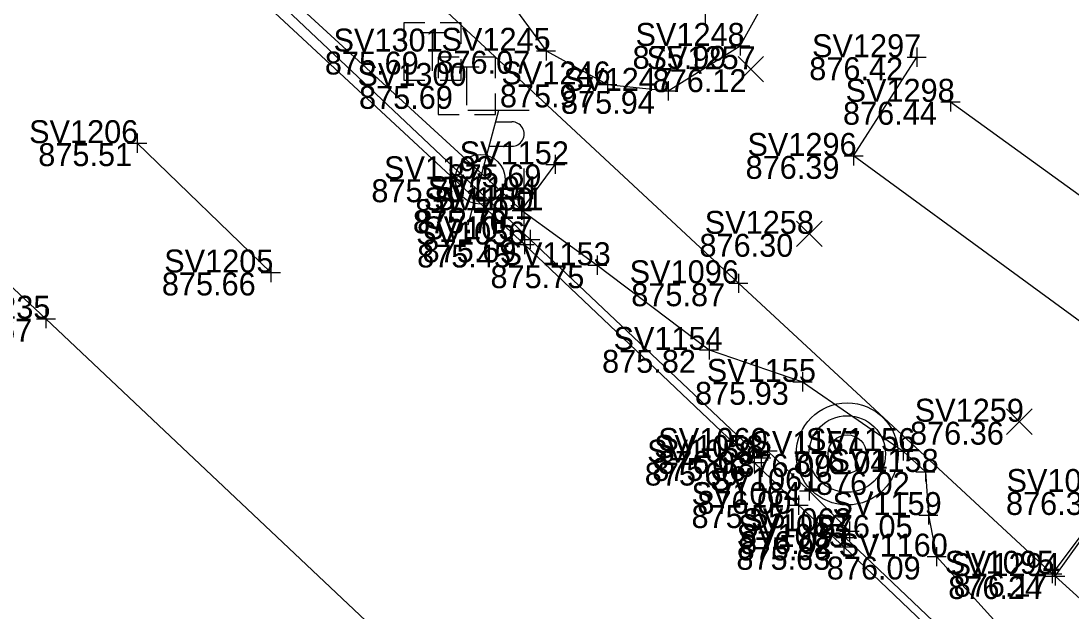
# Model space of a CAD drawing. Extents: x 1480001 to 1480402, y 379235 to 379603.
# Drawn here: x 1480223.3 to 1480278.2, y 379360.8 to 379391.7 of the extents above; entities that cross this region are included whole.
import ezdxf

# ---------------------------------------------------------------- set-up
doc = ezdxf.new("R2010")
doc.units = 0
for name, color, linetype in [('BD_X_Building', 7, 'Continuous'), ('DR_X_Cells', 7, 'Continuous'), ('GK_Drainage_Nodes', 7, 'Continuous'), ('PM_P_CL_Double_Solid', 7, 'Continuous'), ('PM_X_Lane_Line', 7, 'Continuous'), ('PV_X_Curb', 7, 'Continuous'), ('PV_X_Walk', 7, 'Continuous'), ('RD_X_Cells', 7, 'Continuous'), ('SN_X_Public', 7, 'Continuous'), ('SV_X_Random_Point', 7, 'Continuous'), ('SV_X_Shot_Marker', 7, 'Continuous'), ('SV_X_Text_Elevation', 7, 'Continuous'), ('SV_X_Text_Name', 7, 'Continuous'), ('UT_X_Misc_Cells', 7, 'Continuous'), ('UT_X_Telecom_Cells', 7, 'Continuous'), ('UT_X_Water', 7, 'Continuous'), ('VG_X_Flower_Bed', 7, 'Continuous')]:
    doc.layers.add(name, color=color, linetype=linetype)

msp = doc.modelspace()

# ---------------------------------------------------------------- linework, layer by layer
at = {"layer": 'BD_X_Building'}
msp.add_line((1480271.911, 379387.504), (1480306.519, 379362.484), dxfattribs=at)
at = {"layer": 'DR_X_Cells'}
for radius in [2.667, 2, 1]:
    msp.add_circle((1480266.509, 379369.096), radius, dxfattribs=at)
at = {"layer": 'GK_Drainage_Nodes'}
for p, q in [((1480266.509, 379371.096), (1480266.509, 379371.096)), ((1480266.509, 379369.096), (1480266.509, 379369.096)), ((1480266.509, 379369.096), (1480266.509, 379369.096)), ((1480266.509, 379369.096), (1480266.509, 379369.096)), ((1480266.509, 379367.096), (1480266.509, 379367.096))]:
    msp.add_line(p, q, dxfattribs=at)
msp.add_circle((1480266.509, 379369.096), 2, dxfattribs=at)
at = {"layer": 'PM_P_CL_Double_Solid'}
msp.add_lwpolyline([(1480349.171, 379259.048), (1480326.954, 379280.06), (1480305.568, 379299.916), (1480284.393, 379319.578), (1480263.301, 379339.268), (1480242.575, 379359.213), (1480224.612, 379376.165), (1480208.191, 379391.527)], dxfattribs=at)
at = {"layer": 'PM_X_Lane_Line'}
msp.add_line((1480236.368, 379378.582), (1480229.378, 379385.342), dxfattribs=at)
at = {"layer": 'PV_X_Curb'}
for points in [[(1480221.908, 379406.565), (1480233.156, 379396.15), (1480249.934, 379380.311), (1480262.014, 379368.886), (1480262.346, 379369.254), (1480264.513, 379367.165), (1480266.627, 379365.06), (1480266.41, 379364.736), (1480284.493, 379347.537), (1480298.919, 379333.838), (1480300.736, 379332.585), (1480315.855, 379318.308), (1480323.784, 379310.749), (1480324.548, 379310.084), (1480343.241, 379292.305), (1480360.288, 379276.242)], [(1480221.495, 379406.235), (1480232.955, 379395.538), (1480249.633, 379380.044), (1480261.648, 379368.645), (1480263.97, 379366.423), (1480266.337, 379364.241), (1480284.168, 379347.237), (1480298.679, 379333.414), (1480300.396, 379332.229), (1480315.326, 379318.045), (1480323.87, 379309.98), (1480343.087, 379291.663), (1480360.248, 379275.585)]]:
    msp.add_lwpolyline(points, dxfattribs=at)
at = {"layer": 'PV_X_Walk'}
for points in [[(1480355.123, 379297.828), (1480351.285, 379293.6), (1480334.098, 379309.328), (1480328.212, 379315.428), (1480328.737, 379316.329), (1480319.905, 379324.485), (1480307.606, 379335.13), (1480302.895, 379338.359), (1480281.823, 379358.406), (1480285.611, 379363.387), (1480280.441, 379367.109), (1480277.224, 379362.834), (1480260.819, 379378.019), (1480244.572, 379393.153), (1480235.613, 379401.335), (1480215.341, 379421.047)], [(1480304.825, 379363.469), (1480301.807, 379359.476), (1480289.404, 379368.611), (1480281.88, 379358.636), (1480277.384, 379362.714), (1480284.099, 379372.064), (1480266.845, 379384.676), (1480270.146, 379389.834)]]:
    msp.add_lwpolyline(points, dxfattribs=at)
at = {"layer": 'RD_X_Cells'}
msp.add_line((1480259.085, 379392.125), (1480259.085, 379391.593), dxfattribs=at)
at = {"layer": 'SN_X_Public'}
for p, q in [((1480249.601, 379384.014), (1480249.601, 379380.814)), ((1480249.601, 379382.414), (1480248.001, 379382.414))]:
    msp.add_line(p, q, dxfattribs=at)
at = {"layer": 'SV_X_Random_Point'}
for p, q in [((1480260.805, 379388.541), (1480262.139, 379389.876)), ((1480260.805, 379389.876), (1480262.139, 379388.541)), ((1480263.861, 379379.936), (1480265.195, 379381.271)), ((1480263.861, 379381.271), (1480265.195, 379379.936)), ((1480274.842, 379370.114), (1480276.176, 379371.449)), ((1480274.842, 379371.449), (1480276.176, 379370.114))]:
    msp.add_line(p, q, dxfattribs=at)
at = {"layer": 'SV_X_Shot_Marker'}
for p, q in [((1480250.763, 379390.67), (1480250.763, 379389.67)), ((1480260.916, 379390.926), (1480260.916, 379389.926)), ((1480250.263, 379390.17), (1480251.263, 379390.17)), ((1480250.763, 379390.17), (1480250.763, 379390.17)), ((1480260.416, 379390.426), (1480261.416, 379390.426)), ((1480260.916, 379390.426), (1480260.916, 379390.426)), ((1480270.146, 379390.334), (1480270.146, 379389.334)), ((1480269.646, 379389.834), (1480270.646, 379389.834)), ((1480270.146, 379389.834), (1480270.146, 379389.834)), ((1480253.969, 379388.913), (1480253.969, 379387.913)), ((1480253.469, 379388.413), (1480254.469, 379388.413)), ((1480253.969, 379388.413), (1480253.969, 379388.413)), ((1480257.154, 379388.576), (1480257.154, 379387.576)), ((1480256.654, 379388.076), (1480257.654, 379388.076)), ((1480257.154, 379388.076), (1480257.154, 379388.076)), ((1480271.911, 379388.004), (1480271.911, 379387.004)), ((1480271.411, 379387.504), (1480272.411, 379387.504)), ((1480271.911, 379387.504), (1480271.911, 379387.504)), ((1480229.378, 379385.842), (1480229.378, 379384.842)), ((1480228.878, 379385.342), (1480229.878, 379385.342)), ((1480229.378, 379385.342), (1480229.378, 379385.342)), ((1480266.845, 379385.176), (1480266.845, 379384.176)), ((1480251.242, 379384.735), (1480251.242, 379383.735)), ((1480266.345, 379384.676), (1480267.345, 379384.676)), ((1480266.845, 379384.676), (1480266.845, 379384.676)), ((1480250.742, 379384.235), (1480251.742, 379384.235)), ((1480251.242, 379384.235), (1480251.242, 379384.235)), ((1480249.485, 379382.337), (1480249.485, 379381.337)), ((1480249.493, 379382.328), (1480249.493, 379381.328)), ((1480248.985, 379381.837), (1480249.985, 379381.837)), ((1480248.993, 379381.828), (1480249.993, 379381.828)), ((1480249.485, 379381.837), (1480249.485, 379381.837)), ((1480249.493, 379381.828), (1480249.493, 379381.828)), ((1480249.934, 379380.811), (1480249.934, 379379.811)), ((1480249.133, 379380.044), (1480250.133, 379380.044)), ((1480249.434, 379380.311), (1480250.434, 379380.311)), ((1480249.633, 379380.544), (1480249.633, 379379.544)), ((1480249.633, 379380.044), (1480249.633, 379380.044)), ((1480249.934, 379380.311), (1480249.934, 379380.311)), ((1480253.44, 379379.463), (1480253.44, 379378.463)), ((1480236.368, 379379.082), (1480236.368, 379378.082)), ((1480252.94, 379378.963), (1480253.94, 379378.963)), ((1480253.44, 379378.963), (1480253.44, 379378.963)), ((1480235.868, 379378.582), (1480236.868, 379378.582)), ((1480236.368, 379378.582), (1480236.368, 379378.582)), ((1480260.819, 379378.519), (1480260.819, 379377.519)), ((1480260.319, 379378.019), (1480261.319, 379378.019)), ((1480260.819, 379378.019), (1480260.819, 379378.019)), ((1480224.112, 379376.165), (1480225.112, 379376.165)), ((1480224.612, 379376.665), (1480224.612, 379375.665)), ((1480224.612, 379376.165), (1480224.612, 379376.165)), ((1480258.784, 379374.539), (1480259.784, 379374.539)), ((1480259.284, 379375.039), (1480259.284, 379374.039)), ((1480259.284, 379374.539), (1480259.284, 379374.539)), ((1480263.671, 379372.865), (1480264.671, 379372.865)), ((1480264.171, 379373.365), (1480264.171, 379372.365)), ((1480264.171, 379372.865), (1480264.171, 379372.865)), ((1480262.346, 379369.754), (1480262.346, 379368.754)), ((1480269.434, 379369.748), (1480269.434, 379368.748)), ((1480261.648, 379369.145), (1480261.648, 379368.145)), ((1480261.846, 379369.254), (1480262.846, 379369.254)), ((1480262.014, 379369.386), (1480262.014, 379368.386)), ((1480262.346, 379369.254), (1480262.346, 379369.254)), ((1480268.934, 379369.248), (1480269.934, 379369.248)), ((1480269.434, 379369.248), (1480269.434, 379369.248)), ((1480261.148, 379368.645), (1480262.148, 379368.645)), ((1480261.514, 379368.886), (1480262.514, 379368.886)), ((1480261.648, 379368.645), (1480261.648, 379368.645)), ((1480262.014, 379368.886), (1480262.014, 379368.886)), ((1480270.598, 379368.657), (1480270.598, 379367.657)), ((1480270.098, 379368.157), (1480271.098, 379368.157)), ((1480270.598, 379368.157), (1480270.598, 379368.157)), ((1480264.513, 379367.665), (1480264.513, 379366.665)), ((1480263.97, 379366.923), (1480263.97, 379365.923)), ((1480264.013, 379367.165), (1480265.013, 379367.165)), ((1480264.513, 379367.165), (1480264.513, 379367.165)), ((1480263.47, 379366.423), (1480264.47, 379366.423)), ((1480263.97, 379366.423), (1480263.97, 379366.423)), ((1480270.755, 379366.404), (1480270.755, 379365.404)), ((1480270.255, 379365.904), (1480271.255, 379365.904)), ((1480270.755, 379365.904), (1480270.755, 379365.904)), ((1480266.41, 379365.236), (1480266.41, 379364.236)), ((1480266.627, 379365.56), (1480266.627, 379364.56)), ((1480265.91, 379364.736), (1480266.91, 379364.736)), ((1480266.127, 379365.06), (1480267.127, 379365.06)), ((1480266.337, 379364.741), (1480266.337, 379363.741)), ((1480266.41, 379364.736), (1480266.41, 379364.736)), ((1480266.627, 379365.06), (1480266.627, 379365.06)), ((1480265.837, 379364.241), (1480266.837, 379364.241)), ((1480266.337, 379364.241), (1480266.337, 379364.241)), ((1480271.186, 379364.233), (1480271.186, 379363.233)), ((1480270.686, 379363.733), (1480271.686, 379363.733)), ((1480271.186, 379363.733), (1480271.186, 379363.733)), ((1480277.224, 379363.334), (1480277.224, 379362.334)), ((1480277.384, 379363.214), (1480277.384, 379362.214)), ((1480276.724, 379362.834), (1480277.724, 379362.834)), ((1480276.884, 379362.714), (1480277.884, 379362.714)), ((1480277.224, 379362.834), (1480277.224, 379362.834)), ((1480277.384, 379362.714), (1480277.384, 379362.714))]:
    msp.add_line(p, q, dxfattribs=at)
at = {"layer": 'UT_X_Misc_Cells'}
for p, q in [((1480248.279, 379387.055), (1480246.673, 379381.055)), ((1480249.879, 379387.055), (1480246.679, 379387.055)), ((1480248.119, 379386.455), (1480248.969, 379386.455)), ((1480247.778, 379385.18), (1480248.969, 379385.18))]:
    msp.add_line(p, q, dxfattribs=at)
msp.add_circle((1480247.316, 379383.455), 1.3, dxfattribs=at)
msp.add_arc((1480248.982, 379385.818), 0.638, 268.8767, 91.1233, dxfattribs=at)
at = {"layer": 'UT_X_Telecom_Cells'}
for p, q in [((1480244.176, 379391.13), (1480245.476, 379391.13)), ((1480244.826, 379389.13), (1480244.826, 379391.13)), ((1480244.826, 379390.13), (1480244.826, 379390.13)), ((1480245.963, 379389.335), (1480247.263, 379389.335)), ((1480246.613, 379387.335), (1480246.613, 379389.335)), ((1480246.613, 379388.335), (1480246.613, 379388.335))]:
    msp.add_line(p, q, dxfattribs=at)
for points in [[(1480244.426, 379391.63), (1480243.326, 379391.63), (1480243.326, 379390.53)], [(1480246.326, 379390.53), (1480246.326, 379391.63), (1480245.226, 379391.63)], [(1480243.326, 379389.73), (1480243.326, 379388.63), (1480244.426, 379388.63)], [(1480246.213, 379389.835), (1480245.113, 379389.835), (1480245.113, 379388.735)], [(1480245.226, 379388.63), (1480246.326, 379388.63), (1480246.326, 379389.73)], [(1480248.113, 379388.735), (1480248.113, 379389.835), (1480247.013, 379389.835)], [(1480245.113, 379387.935), (1480245.113, 379386.835), (1480246.213, 379386.835)], [(1480247.013, 379386.835), (1480248.113, 379386.835), (1480248.113, 379387.935)]]:
    msp.add_lwpolyline(points, dxfattribs=at)
at = {"layer": 'UT_X_Water'}
msp.add_line((1480249.485, 379381.837), (1480251.242, 379384.235), dxfattribs=at)
msp.add_lwpolyline([(1480212.628, 379415.684), (1480231.592, 379398.237), (1480249.493, 379381.828), (1480253.44, 379378.963), (1480259.284, 379374.539), (1480264.171, 379372.865), (1480269.434, 379369.248), (1480270.598, 379368.157), (1480270.755, 379365.904), (1480271.186, 379363.733), (1480285.468, 379347.959), (1480298.848, 379335.614), (1480313.013, 379322.705), (1480330.745, 379305.601), (1480344.344, 379292.312), (1480351.783, 379285.136)], dxfattribs=at)
at = {"layer": 'VG_X_Flower_Bed'}
msp.add_lwpolyline([(1480259.84, 379404.335), (1480257.924, 379405.748), (1480255.177, 379406.249), (1480251.852, 379406.017), (1480249.014, 379405.214), (1480246.824, 379402.725), (1480245.84, 379401.059), (1480245.489, 379397.92), (1480248.239, 379393.61), (1480250.763, 379390.17), (1480253.969, 379388.413), (1480257.154, 379388.076), (1480260.916, 379390.426), (1480263.531, 379395.15), (1480263.215, 379398.861), (1480260.704, 379403.535)], dxfattribs=at)

# ---------------------------------------------------------------- texts
at = {"layer": 'SV_X_Text_Elevation'}
for s, p in [('875.99', (1480255.285, 379389.226)), ('875.69', (1480239.195, 379388.93)), ('876.07', (1480245.028, 379388.97)), ('876.42', (1480264.524, 379388.634)), ('876.12', (1480256.333, 379388.008)), ('875.69', (1480240.982, 379387.135)), ('875.97', (1480248.347, 379387.213)), ('875.94', (1480251.542, 379386.876)), ('876.44', (1480266.289, 379386.304)), ('875.51', (1480224.209, 379384.142)), ('876.39', (1480261.195, 379383.476)), ('875.69', (1480245.611, 379383.035)), ('875.70', (1480241.628, 379382.255)), ('875.70', (1480243.913, 379381.214)), ('875.70', (1480243.797, 379380.637)), ('875.70', (1480243.805, 379380.628)), ('876.30', (1480258.783, 379379.403)), ('875.45', (1480244.021, 379378.844)), ('875.69', (1480244.303, 379379.111)), ('875.75', (1480247.856, 379377.763)), ('875.66', (1480230.671, 379377.382)), ('875.87', (1480255.216, 379376.819)), ('875.67', (1480218.99, 379374.965)), ('875.82', (1480253.691, 379373.339)), ('875.93', (1480258.549, 379371.665)), ('876.36', (1480269.793, 379369.582)), ('876.02', (1480256.62, 379368.054)), ('876.09', (1480260.764, 379367.896)), ('876.04', (1480263.708, 379368.048)), ('875.60', (1480255.922, 379367.445)), ('875.96', (1480256.317, 379367.686)), ('876.02', (1480264.872, 379366.957)), ('876.00', (1480258.674, 379365.965)), ('876.32', (1480274.81, 379365.909)), ('875.55', (1480258.367, 379365.223)), ('876.05', (1480265.02, 379364.704)), ('875.98', (1480260.779, 379363.536)), ('876.02', (1480260.901, 379363.86)), ('875.63', (1480260.715, 379363.041)), ('876.09', (1480265.441, 379362.533)), ('876.24', (1480271.791, 379361.514)), ('876.17', (1480272.075, 379361.634))]:
    msp.add_text(s, height=1.2, dxfattribs=at).set_placement(p)
at = {"layer": 'SV_X_Text_Name'}
for s, p in [('SV1248', (1480255.437, 379390.426)), ('SV1301', (1480239.648, 379390.13)), ('SV1245', (1480245.293, 379390.17)), ('SV1297', (1480264.667, 379389.834)), ('SV1257', (1480256.012, 379389.208)), ('SV1300', (1480240.897, 379388.335)), ('SV1246', (1480248.424, 379388.413)), ('SV1247', (1480251.684, 379388.076)), ('SV1298', (1480266.422, 379387.504)), ('SV1206', (1480223.729, 379385.342)), ('SV1296', (1480261.29, 379384.676)), ('SV1152', (1480246.245, 379384.235)), ('SV1193', (1480242.291, 379383.455)), ('SV1194', (1480244.585, 379382.414)), ('SV1150', (1480244.383, 379381.828)), ('SV1151', (1480244.913, 379381.837)), ('SV1258', (1480259.058, 379380.603)), ('SV1056', (1480243.965, 379380.044)), ('SV1057', (1480244.341, 379380.311)), ('SV1153', (1480248.434, 379378.963)), ('SV1205', (1480230.794, 379378.582)), ('SV1096', (1480255.132, 379378.019)), ('SV1235', (1480219.133, 379376.165)), ('SV1154', (1480254.287, 379374.539)), ('SV1155', (1480259.165, 379372.865)), ('SV1259', (1480270.039, 379370.782)), ('SV1060', (1480256.63, 379369.254)), ('SV1157', (1480261.503, 379369.096)), ('SV1156', (1480264.352, 379369.248)), ('SV1059', (1480256.046, 379368.645)), ('SV1058', (1480256.412, 379368.886)), ('SV1158', (1480265.582, 379368.157)), ('SV1061', (1480259.335, 379367.165)), ('SV1094', (1480274.839, 379367.109)), ('SV1064', (1480258.368, 379366.423)), ('SV1159', (1480265.739, 379365.904)), ('SV1062', (1480261.025, 379365.06)), ('SV1063', (1480260.798, 379364.736)), ('SV1065', (1480260.725, 379364.241)), ('SV1160', (1480266.057, 379363.733)), ('SV1095', (1480271.612, 379362.834)), ('SV1294', (1480271.914, 379362.714))]:
    msp.add_text(s, height=1.2, dxfattribs=at).set_placement(p)

doc.saveas('drawing.dxf')
